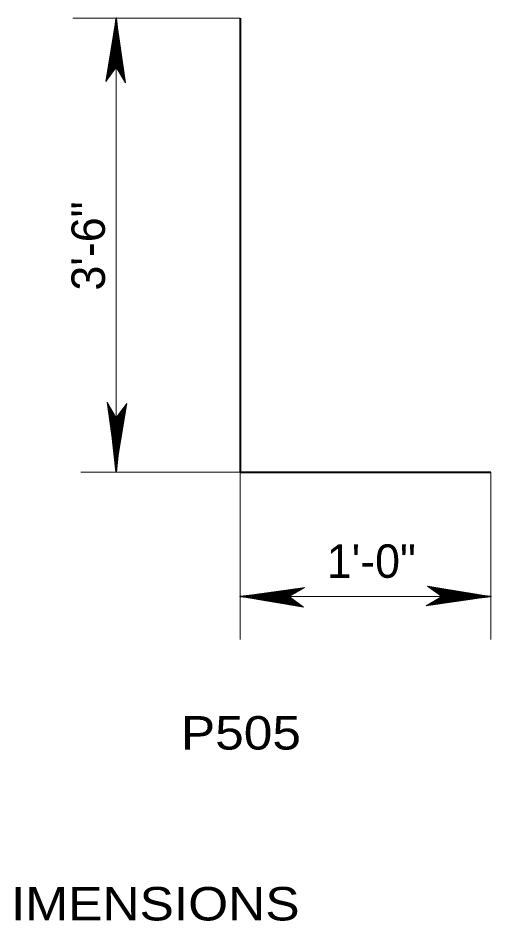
# Model space of a CAD drawing. Extents: x 144 to 252, y 360 to 425.
# Drawn here: x 216.11 to 220.12, y 380.81 to 388.45 of the extents above; entities that cross this region are included whole.
import ezdxf

# ---------------------------------------------------------------- set-up
doc = ezdxf.new("R2010")
doc.units = 0
doc.header["$LTSCALE"] = 0.13
doc.layers.add('1', color=7, linetype='Continuous', lineweight=40)
doc.layers.add('3', color=7, linetype='Continuous', lineweight=13)

msp = doc.modelspace()

# ---------------------------------------------------------------- linework, layer by layer
at = {"layer": '1', "lineweight": 13}
for p, q in [((217.9912, 388.4547), (216.5746, 388.4547)), ((216.9429, 388.4547), (216.9429, 384.6552)), ((217.9912, 384.6128), (216.6412, 384.6128)), ((217.9912, 384.6128), (217.9912, 383.1961)), ((220.1162, 384.6128), (220.1162, 383.1961)), ((217.9912, 383.5587), (220.1162, 383.5587))]:
    msp.add_line(p, q, dxfattribs=at)
at = {"layer": '1', "lineweight": 35}
for p, q in [((216.9429, 388.0949), (216.9429, 388.4547)), ((216.9089, 388.1034), (216.9401, 388.3698)), ((216.9089, 388.1034), (216.9401, 388.3698)), ((216.9117, 388.1034), (216.9401, 388.3698)), ((216.9146, 388.1034), (216.9429, 388.3698)), ((216.9146, 388.1034), (216.9486, 388.3698)), ((216.9656, 388.1006), (216.9401, 388.3499)), ((216.9712, 388.1034), (216.9429, 388.3528)), ((216.9741, 388.1034), (216.9486, 388.3528)), ((216.9797, 388.1034), (216.9514, 388.3528)), ((216.9061, 384.9641), (216.9344, 384.7147)), ((216.9117, 384.9641), (216.9373, 384.7147)), ((216.9146, 384.9641), (216.9429, 384.7147)), ((216.9202, 384.9669), (216.9458, 384.7176)), ((216.9712, 384.9641), (216.9373, 384.6977)), ((216.9429, 384.9726), (216.9429, 384.6128)), ((216.9712, 384.9641), (216.9429, 384.6977)), ((216.9769, 384.9641), (216.9458, 384.6977)), ((216.9769, 384.9641), (216.9458, 384.6977)), ((216.9741, 384.9641), (216.9458, 384.6977)), ((218.3426, 383.5956), (218.0932, 383.5673)), ((218.3426, 383.5899), (218.0932, 383.5644)), ((218.3426, 383.5871), (218.0932, 383.5587)), ((219.7649, 383.5927), (220.0312, 383.5616)), ((219.7649, 383.5927), (220.0312, 383.5616)), ((219.7649, 383.5899), (220.0312, 383.5616)), ((219.7649, 383.5871), (220.0312, 383.5587)), ((219.7649, 383.5871), (220.0312, 383.5531)), ((218.3511, 383.5587), (217.9912, 383.5587)), ((218.3426, 383.5304), (218.0762, 383.5644)), ((218.3426, 383.5304), (218.0762, 383.5587)), ((218.3426, 383.5247), (218.0762, 383.5559)), ((218.3426, 383.5247), (218.0762, 383.5559)), ((218.3426, 383.5276), (218.0762, 383.5559)), ((218.3454, 383.5814), (218.0961, 383.5559)), ((219.7564, 383.5587), (220.1162, 383.5587)), ((219.7621, 383.5361), (220.0114, 383.5616)), ((219.7649, 383.5304), (220.0143, 383.5587)), ((219.7649, 383.5276), (220.0143, 383.5531)), ((219.7649, 383.5219), (220.0143, 383.5503))]:
    msp.add_line(p, q, dxfattribs=at)
for points in [[(216.9061, 388.0949), (216.9429, 388.4547), (216.9826, 388.0949), (216.9429, 388.1148)], [(216.9401, 388.1204), (216.9373, 388.2791), (216.9401, 388.2791), (216.9401, 388.2479), (216.9373, 388.1204), (216.9344, 388.2224), (216.9316, 388.1148), (216.9287, 388.1912), (216.9259, 388.1148), (216.9344, 388.2337), (216.9401, 388.3924), (216.9486, 388.3612), (216.9486, 388.4038), (216.9486, 388.1204), (216.9543, 388.2026), (216.9543, 388.1148), (216.9401, 388.2961), (216.9627, 388.1148)], [(216.9797, 384.9726), (216.9429, 384.6128), (216.9032, 384.9726), (216.9429, 384.9527)], [(216.9458, 384.9471), (216.9486, 384.7884), (216.9458, 384.7884), (216.9458, 384.8196), (216.9486, 384.9471), (216.9514, 384.8451), (216.9543, 384.9527), (216.9571, 384.8762), (216.9599, 384.9527), (216.9514, 384.8338), (216.9458, 384.6751), (216.9373, 384.7063), (216.9373, 384.6637), (216.9373, 384.9471), (216.9316, 384.8649), (216.9316, 384.9527), (216.9458, 384.7714), (216.9231, 384.9527)], [(218.3511, 383.5219), (217.9912, 383.5587), (218.3511, 383.5984), (218.3312, 383.5587)], [(219.7564, 383.5956), (220.1162, 383.5587), (219.7564, 383.5191), (219.7763, 383.5587)], [(218.3256, 383.5559), (218.1669, 383.5531), (218.1669, 383.5559), (218.1981, 383.5559), (218.3256, 383.5531), (218.2236, 383.5503), (218.3312, 383.5474), (218.2548, 383.5446), (218.3312, 383.5417), (218.2122, 383.5503), (218.0536, 383.5559), (218.0847, 383.5644), (218.0422, 383.5644), (218.3256, 383.5644), (218.2434, 383.5701), (218.3312, 383.5701), (218.1499, 383.5559), (218.3312, 383.5786)], [(219.7819, 383.5616), (219.9406, 383.5644), (219.9406, 383.5616), (219.9094, 383.5616), (219.7819, 383.5644), (219.8839, 383.5673), (219.7763, 383.5701), (219.8527, 383.5729), (219.7763, 383.5757), (219.8953, 383.5673), (220.0539, 383.5616), (220.0228, 383.5531), (220.0652, 383.5531), (219.7819, 383.5531), (219.8641, 383.5474), (219.7763, 383.5474), (219.9576, 383.5616), (219.7763, 383.5389)]]:
    msp.add_lwpolyline(points, close=True, dxfattribs=at)
at = {"layer": '1'}
msp.add_lwpolyline([(217.9912, 388.4547), (217.9912, 384.6128), (220.1162, 384.6128)], dxfattribs=at)
at = {"layer": '1', "lineweight": 35}
for points in [[(216.9401, 388.1204), (216.9146, 388.1062), (216.9231, 388.1148), (216.9344, 388.1204), (216.9316, 388.1289), (216.9202, 388.1232), (216.9458, 388.1176), (216.9627, 388.1119), (216.9769, 388.1034)], [(216.9458, 384.9471), (216.9712, 384.9613), (216.9627, 384.9527), (216.9514, 384.9471), (216.9543, 384.9386), (216.9656, 384.9443), (216.9401, 384.9499), (216.9231, 384.9556), (216.9089, 384.9641)], [(218.3256, 383.5559), (218.3397, 383.5304), (218.3312, 383.5389), (218.3256, 383.5503), (218.3171, 383.5474), (218.3227, 383.5361), (218.3284, 383.5616), (218.3341, 383.5786), (218.3426, 383.5927)], [(219.7819, 383.5616), (219.7678, 383.5871), (219.7763, 383.5786), (219.7819, 383.5673), (219.7904, 383.5701), (219.7848, 383.5814), (219.7791, 383.5559), (219.7734, 383.5389), (219.7649, 383.5247)]]:
    msp.add_lwpolyline(points, dxfattribs=at)
at = {"layer": '3'}
for p, q in [((216.9429, 388.4547), (216.8537, 387.9171)), ((216.9423, 388.4403), (216.856, 387.9203)), ((216.9423, 388.4295), (216.8583, 387.9236)), ((216.9423, 388.4151), (216.8615, 387.9278)), ((216.9423, 388.4023), (216.8642, 387.9316)), ((217.0172, 387.912), (216.9423, 388.4403)), ((217.0152, 387.9155), (216.9423, 388.4295)), ((217.0125, 387.9201), (216.9423, 388.4151)), ((217.0101, 387.9242), (216.9423, 388.4023)), ((217.0101, 387.9242), (216.9423, 388.4023)), ((216.9429, 388.0393), (216.9429, 388.4547)), ((217.0207, 387.906), (216.9429, 388.4547)), ((216.9423, 388.391), (216.8666, 387.9349)), ((216.9423, 388.3766), (216.8697, 387.9392)), ((216.9423, 388.3638), (216.8725, 387.9429)), ((216.9423, 388.3501), (216.8754, 387.947)), ((216.9423, 388.3363), (216.8784, 387.9511)), ((216.9423, 388.323), (216.8812, 387.955)), ((217.0079, 387.9278), (216.9423, 388.391)), ((217.0052, 387.9324), (216.9423, 388.3766)), ((217.0028, 387.9365), (216.9423, 388.3638)), ((217.0003, 387.9409), (216.9423, 388.3501)), ((216.9977, 387.9453), (216.9423, 388.3363)), ((216.9952, 387.9496), (216.9423, 388.323)), ((216.9423, 388.3091), (216.8842, 387.9591)), ((216.9423, 388.2965), (216.8869, 387.9628)), ((216.9423, 388.2851), (216.8894, 387.9663)), ((216.9423, 388.2694), (216.8928, 387.9708)), ((216.9423, 388.2556), (216.8957, 387.9749)), ((216.9926, 387.9541), (216.9423, 388.3091)), ((216.9903, 387.9581), (216.9423, 388.2965)), ((216.9881, 387.9618), (216.9423, 388.2851)), ((216.9852, 387.9668), (216.9423, 388.2694)), ((216.9826, 387.9712), (216.9423, 388.2556)), ((216.9417, 388.2376), (216.8988, 387.9792)), ((216.9417, 388.2237), (216.9018, 387.9833)), ((216.9417, 388.2105), (216.9047, 387.9872)), ((216.9423, 388.2014), (216.9074, 387.9909)), ((216.9423, 388.1894), (216.91, 387.9945)), ((216.9423, 388.1756), (216.913, 387.9986)), ((216.9784, 387.9784), (216.9417, 388.2376)), ((216.9758, 387.9828), (216.9417, 388.2237)), ((216.9733, 387.9871), (216.9417, 388.2105)), ((216.9725, 387.9886), (216.9423, 388.2014)), ((216.9702, 387.9925), (216.9423, 388.1894)), ((216.9676, 387.9969), (216.9423, 388.1756)), ((216.9803, 387.9752), (216.9433, 388.236)), ((216.9423, 388.1599), (216.9162, 388.0032)), ((216.9423, 388.1473), (216.919, 388.0069)), ((216.9423, 388.1341), (216.9218, 388.0108)), ((216.9423, 388.1221), (216.9245, 388.0144)), ((216.9423, 388.1076), (216.9275, 388.0187)), ((216.9423, 388.0938), (216.9305, 388.0228)), ((216.9647, 388.0019), (216.9423, 388.1599)), ((216.9623, 388.006), (216.9423, 388.1473)), ((216.9598, 388.0102), (216.9423, 388.1341)), ((216.9576, 388.0141), (216.9423, 388.1221)), ((216.9549, 388.0188), (216.9423, 388.1076)), ((216.9523, 388.0232), (216.9423, 388.0938)), ((216.8537, 387.9171), (216.9427, 388.0396)), ((216.9423, 388.0811), (216.9332, 388.0265)), ((216.9423, 388.0678), (216.9361, 388.0304)), ((216.9423, 388.0564), (216.9385, 388.0338)), ((216.9423, 388.0462), (216.9407, 388.0368)), ((216.95, 388.0272), (216.9423, 388.0811)), ((216.9453, 388.0352), (216.9423, 388.0564)), ((216.9427, 388.0396), (217.0207, 387.906)), ((216.9469, 388.0325), (216.9433, 388.0576)), ((216.8652, 385.204), (216.9429, 384.6552)), ((216.9431, 385.0704), (216.8652, 385.204)), ((216.8687, 385.198), (216.9436, 384.6697)), ((216.8707, 385.1945), (216.9436, 384.6805)), ((216.8733, 385.1899), (216.9436, 384.6949)), ((216.9429, 384.6552), (217.0322, 385.1929)), ((217.0322, 385.1929), (216.9431, 385.0704)), ((216.9436, 384.6697), (217.0298, 385.1897)), ((216.8757, 385.1858), (216.9436, 384.7077)), ((216.8757, 385.1858), (216.9436, 384.7077)), ((216.8779, 385.1822), (216.9436, 384.719)), ((216.8806, 385.1776), (216.9436, 384.7334)), ((216.883, 385.1735), (216.9436, 384.7462)), ((216.8855, 385.1691), (216.9436, 384.7599)), ((216.8881, 385.1647), (216.9436, 384.7738)), ((216.8906, 385.1604), (216.9436, 384.787)), ((216.8932, 385.1559), (216.9436, 384.8009)), ((216.8955, 385.1519), (216.9436, 384.8135)), ((216.8978, 385.1482), (216.9436, 384.8249)), ((216.9006, 385.1432), (216.9436, 384.8406)), ((216.9032, 385.1387), (216.9436, 384.8544)), ((216.9055, 385.1347), (216.9425, 384.874)), ((216.9074, 385.1316), (216.9441, 384.8724)), ((216.91, 385.1272), (216.9441, 384.8863)), ((216.9125, 385.1229), (216.9441, 384.8995)), ((216.9133, 385.1214), (216.9436, 384.9086)), ((216.9156, 385.1175), (216.9436, 384.9206)), ((216.9183, 385.1131), (216.9436, 384.9344)), ((216.9436, 384.6805), (217.0275, 385.1864)), ((216.9436, 384.6949), (217.0243, 385.1822)), ((216.9436, 384.7077), (217.0217, 385.1784)), ((216.9436, 384.719), (217.0192, 385.1751)), ((216.9436, 384.7334), (217.0161, 385.1708)), ((216.9436, 384.7462), (217.0133, 385.1671)), ((216.9436, 384.7599), (217.0104, 385.163)), ((216.9436, 384.7738), (217.0074, 385.1589)), ((216.9436, 384.787), (217.0046, 385.155)), ((216.9436, 384.8009), (217.0016, 385.1509)), ((216.9436, 384.8135), (216.9989, 385.1472)), ((216.9436, 384.8249), (216.9964, 385.1438)), ((216.9436, 384.8406), (216.9931, 385.1392)), ((216.9436, 384.8544), (216.9901, 385.1351)), ((216.9436, 384.9086), (216.9784, 385.1191)), ((216.9436, 384.9206), (216.9758, 385.1155)), ((216.9441, 384.8724), (216.987, 385.1308)), ((216.9441, 384.8863), (216.984, 385.1267)), ((216.9441, 384.8995), (216.9812, 385.1228)), ((216.9211, 385.1081), (216.9436, 384.9501)), ((216.9235, 385.104), (216.9436, 384.9627)), ((216.926, 385.0997), (216.9436, 384.9759)), ((216.9282, 385.0959), (216.9436, 384.9879)), ((216.9309, 385.0913), (216.9436, 385.0024)), ((216.9335, 385.0868), (216.9436, 385.0163)), ((216.9358, 385.0827), (216.9436, 385.0289)), ((216.9389, 385.0775), (216.9425, 385.0524)), ((216.9405, 385.0748), (216.9436, 385.0536)), ((216.9429, 385.0707), (216.9429, 384.6552)), ((216.9436, 384.9344), (216.9728, 385.1114)), ((216.9436, 384.9501), (216.9696, 385.1067)), ((216.9436, 384.9627), (216.9668, 385.1031)), ((216.9436, 384.9759), (216.964, 385.0992)), ((216.9436, 384.9879), (216.9613, 385.0956)), ((216.9436, 385.0024), (216.9583, 385.0913)), ((216.9436, 385.0163), (216.9553, 385.0872)), ((216.9436, 385.0289), (216.9526, 385.0835)), ((216.9436, 385.0422), (216.9497, 385.0796)), ((216.9436, 385.0536), (216.9473, 385.0762)), ((216.9436, 385.0637), (216.9451, 385.0732)), ((218.54, 383.6365), (217.9912, 383.5587)), ((218.534, 383.633), (218.0057, 383.5581)), ((218.5305, 383.631), (218.0165, 383.5581)), ((218.5259, 383.6283), (218.0309, 383.5581)), ((218.5218, 383.6259), (218.0437, 383.5581)), ((218.5218, 383.6259), (218.0437, 383.5581)), ((218.5182, 383.6237), (218.055, 383.5581)), ((218.5136, 383.6211), (218.0694, 383.5581)), ((218.5095, 383.6187), (218.0822, 383.5581)), ((218.5051, 383.6162), (218.0959, 383.5581)), ((218.5007, 383.6136), (218.1097, 383.5581)), ((218.4964, 383.6111), (218.123, 383.5581)), ((218.4919, 383.6084), (218.1369, 383.5581)), ((218.4879, 383.6062), (218.1495, 383.5581)), ((218.4842, 383.6039), (218.1609, 383.5581)), ((218.4792, 383.6011), (218.1766, 383.5581)), ((218.4748, 383.5984), (218.1904, 383.5581)), ((218.4676, 383.5942), (218.2084, 383.5576)), ((218.4707, 383.5962), (218.21, 383.5592)), ((218.4632, 383.5917), (218.2223, 383.5576)), ((218.4589, 383.5892), (218.2355, 383.5576)), ((218.4574, 383.5883), (218.2446, 383.5581)), ((218.4535, 383.5861), (218.2566, 383.5581)), ((218.4064, 383.5586), (218.54, 383.6365)), ((220.1162, 383.5587), (219.5786, 383.648)), ((219.5786, 383.648), (219.7011, 383.5589)), ((220.1018, 383.5594), (219.5818, 383.6457)), ((220.091, 383.5594), (219.5851, 383.6433)), ((220.0766, 383.5594), (219.5893, 383.6402)), ((220.0638, 383.5594), (219.5931, 383.6375)), ((220.0525, 383.5594), (219.5964, 383.6351)), ((220.0381, 383.5594), (219.6007, 383.6319)), ((220.0253, 383.5594), (219.6044, 383.6292)), ((220.0116, 383.5594), (219.6085, 383.6262)), ((219.9977, 383.5594), (219.6126, 383.6232)), ((219.9845, 383.5594), (219.6165, 383.6204)), ((219.9706, 383.5594), (219.6206, 383.6174)), ((219.958, 383.5594), (219.6243, 383.6148)), ((219.9466, 383.5594), (219.6277, 383.6122)), ((219.9309, 383.5594), (219.6323, 383.6089)), ((219.9171, 383.5594), (219.6364, 383.6059)), ((219.8991, 383.5599), (219.6407, 383.6028)), ((219.8852, 383.5599), (219.6448, 383.5998)), ((219.872, 383.5599), (219.6487, 383.597)), ((219.8629, 383.5594), (219.6524, 383.5942)), ((219.8509, 383.5594), (219.656, 383.5917)), ((219.8371, 383.5594), (219.6601, 383.5887)), ((219.8214, 383.5594), (219.6647, 383.5854)), ((217.9912, 383.5587), (218.5289, 383.4695)), ((218.4067, 383.5587), (217.9912, 383.5587)), ((218.0057, 383.5581), (218.5257, 383.4718)), ((218.0165, 383.5581), (218.5224, 383.4742)), ((218.0309, 383.5581), (218.5182, 383.4773)), ((218.0437, 383.5581), (218.5144, 383.48)), ((218.055, 383.5581), (218.5111, 383.4824)), ((218.0694, 383.5581), (218.5068, 383.4856)), ((218.0822, 383.5581), (218.5031, 383.4883)), ((218.0959, 383.5581), (218.499, 383.4912)), ((218.1097, 383.5581), (218.4949, 383.4942)), ((218.123, 383.5581), (218.491, 383.4971)), ((218.1369, 383.5581), (218.4869, 383.5001)), ((218.1495, 383.5581), (218.4832, 383.5027)), ((218.1609, 383.5581), (218.4797, 383.5052)), ((218.1766, 383.5581), (218.4752, 383.5086)), ((218.1904, 383.5581), (218.4711, 383.5116)), ((218.2084, 383.5576), (218.4668, 383.5147)), ((218.2223, 383.5576), (218.4627, 383.5177)), ((218.2355, 383.5576), (218.4588, 383.5205)), ((218.2446, 383.5581), (218.4551, 383.5232)), ((218.2566, 383.5581), (218.4515, 383.5258)), ((218.4491, 383.5834), (218.2704, 383.5581)), ((218.2704, 383.5581), (218.4474, 383.5288)), ((218.4441, 383.5806), (218.2861, 383.5581)), ((218.2861, 383.5581), (218.4427, 383.5321)), ((218.44, 383.5782), (218.2987, 383.5581)), ((218.2987, 383.5581), (218.4391, 383.5348)), ((218.4357, 383.5757), (218.3119, 383.5581)), ((218.3119, 383.5581), (218.4352, 383.5377)), ((218.4319, 383.5734), (218.3239, 383.5581)), ((218.3239, 383.5581), (218.4316, 383.5403)), ((218.4272, 383.5707), (218.3384, 383.5581)), ((218.3384, 383.5581), (218.4273, 383.5433)), ((218.4228, 383.5682), (218.3522, 383.5581)), ((218.3522, 383.5581), (218.4232, 383.5463)), ((218.4187, 383.5658), (218.3649, 383.5581)), ((218.3649, 383.5581), (218.4195, 383.5491)), ((218.3782, 383.5581), (218.4156, 383.5519)), ((218.4135, 383.5627), (218.3884, 383.5592)), ((218.4108, 383.5612), (218.3896, 383.5581)), ((218.3896, 383.5581), (218.4122, 383.5543)), ((218.3997, 383.5581), (218.4092, 383.5566)), ((218.5289, 383.4695), (218.4064, 383.5586)), ((219.7011, 383.5589), (219.5675, 383.481)), ((219.5675, 383.481), (220.1162, 383.5587)), ((219.5735, 383.4845), (220.1018, 383.5594)), ((219.577, 383.4865), (220.091, 383.5594)), ((219.5816, 383.4892), (220.0766, 383.5594)), ((219.5857, 383.4916), (220.0638, 383.5594)), ((219.5857, 383.4916), (220.0638, 383.5594)), ((219.5893, 383.4937), (220.0525, 383.5594)), ((219.5939, 383.4964), (220.0381, 383.5594)), ((219.598, 383.4988), (220.0253, 383.5594)), ((219.6024, 383.5013), (220.0116, 383.5594)), ((219.6068, 383.5039), (219.9977, 383.5594)), ((219.6111, 383.5064), (219.9845, 383.5594)), ((219.6156, 383.5091), (219.9706, 383.5594)), ((219.6196, 383.5113), (219.958, 383.5594)), ((219.6233, 383.5136), (219.9466, 383.5594)), ((219.6283, 383.5164), (219.9309, 383.5594)), ((219.6327, 383.5191), (219.9171, 383.5594)), ((219.6368, 383.5213), (219.8975, 383.5583)), ((219.6399, 383.5232), (219.8991, 383.5599)), ((219.6443, 383.5258), (219.8852, 383.5599)), ((219.6486, 383.5283), (219.872, 383.5599)), ((219.6501, 383.5292), (219.8629, 383.5594)), ((219.654, 383.5314), (219.8509, 383.5594)), ((219.6584, 383.5341), (219.8371, 383.5594)), ((219.6634, 383.5369), (219.8214, 383.5594)), ((219.6675, 383.5393), (219.8088, 383.5594)), ((219.8088, 383.5594), (219.6684, 383.5827)), ((219.6718, 383.5418), (219.7956, 383.5594)), ((219.7956, 383.5594), (219.6723, 383.5798)), ((219.6756, 383.5441), (219.7836, 383.5594)), ((219.7836, 383.5594), (219.6759, 383.5772)), ((219.7691, 383.5594), (219.6802, 383.5742)), ((219.6803, 383.5467), (219.7691, 383.5594)), ((219.7552, 383.5594), (219.6843, 383.5712)), ((219.6847, 383.5493), (219.7552, 383.5594)), ((219.7426, 383.5594), (219.688, 383.5684)), ((219.6887, 383.5517), (219.7426, 383.5594)), ((219.7293, 383.5594), (219.6919, 383.5656)), ((219.694, 383.5548), (219.7191, 383.5583)), ((219.7179, 383.5594), (219.6953, 383.5632)), ((219.6967, 383.5563), (219.7179, 383.5594)), ((219.7078, 383.5594), (219.6983, 383.5609)), ((219.7008, 383.5587), (220.1162, 383.5587))]:
    msp.add_line(p, q, dxfattribs=at)

# ---------------------------------------------------------------- texts
at = {"layer": '1'}
msp.add_text('3\'-6"', height=0.2833, rotation=90, dxfattribs=at).set_placement((216.8466, 386.1484))
msp.add_text('1\'-0"', height=0.2833, dxfattribs=at).set_placement((218.7259, 383.7173))
at = {"layer": '1', "width": 1.15}
for s, p in [('P505', (217.4897, 382.2639)), ('NOTE: ALL REBAR DIMENSIONS', (211.7657, 380.8176))]:
    msp.add_text(s, height=0.2833, dxfattribs=at).set_placement(p)

doc.saveas('drawing.dxf')
